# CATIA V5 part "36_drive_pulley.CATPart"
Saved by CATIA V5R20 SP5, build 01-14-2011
Part number: 36_drive_pulley
Bounding box of the stored display mesh (mm): x -11.997 to 11.997, y 21.365 to 45.359, z -174.5 to -155.5
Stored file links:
  C:\Documents and Settings\anizard\Bureau\13\36_drive_pulley.CATPart
  C:\Documents and Settings\anizard\Bureau\13\anizard.CATProduct
  C:\Documents and Settings\anizard\Bureau\13\16_C-shaped_bracket.CATPart
  D:\Documents\T\2011-2012\CFAO\ThinkMotion\7\SqueletteV.CATPart
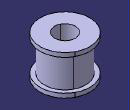
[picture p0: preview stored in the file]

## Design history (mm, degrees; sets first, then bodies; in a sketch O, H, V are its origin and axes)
Set1
  Line1: linked copy from another document
  Plane1: linked copy from another document
  Point1: linked copy from another document
  Plane2 to Plane4: linked copy from another document
  Point2: linked copy from another document
  Point3: linked copy from another document
Body1 (main body)
  Sketch1 on yz-plane, origin (0, 0, 0), H (0, 1, 0), V (0, 0, 1)
    line L1 (38.3619, -174.5) -> (38.3619, -155.5)
    line L2 (38.3619, -155.5) -> (45.3619, -155.5)
    line L3 (45.3619, -155.5) -> (45.3619, -157.5)
    line L4 (45.3619, -157.5) -> (43.3619, -157.5)
    line L5 (43.3619, -157.5) -> (43.3619, -172.5)
    line L6 (43.3619, -172.5) -> (45.3619, -172.5)
    point P7 (45.3619, -172.5)
    line L7 (45.3619, -172.5) -> (45.3619, -174.5)
    line L8 (45.3619, -174.5) -> (38.3619, -174.5)
    reference intersected line E1 through (0, -155.5) direction (1, 0) from Plane1
    reference projected point E2 (38.3619, -155.5) from Point1
    reference intersected line E3 through (0, -157.5) direction (-1, 0) from Plane2
    reference intersected line E4 through (0, -172.5) direction (-1, 0) from Plane3
    reference intersected line E5 through (0, -174.5) direction (-1, 0) from Plane4
    reference projected point E6 (43.3619, -155.5) from Point3
    distance L5 L7 = 2
    vertical: L1 V, L3 V, L5 V, L7 V
    horizontal: L2 H, L4 H, L6 H, L8 H
    coincidence: P7 L3, L2 E1, L1 E2, L4 E3, L6 E4, L8 E5, L5 E6
  Shaft1: profile Sketch1, axis Line1, angle 360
